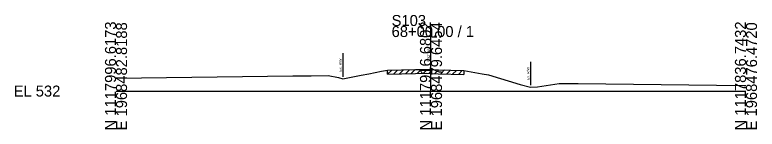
# Model space of a CAD drawing. Extents: x -26 to 163, y -10 to 24018.
# Drawn here: x -25.7 to 162.8, y 15990.3 to 16019.4 of the extents above; entities that cross this region are included whole.
import ezdxf

# ---------------------------------------------------------------- set-up
doc = ezdxf.new("R2010")
doc.units = 0
for name, color, linetype in [('RD_GPK_XS_Cell', 7, 'Continuous'), ('RD_XS_ExGround', 7, 'Continuous'), ('RD_XS_ExPaveRet', 7, 'Continuous'), ('RD_XS_ExRW', 7, 'Continuous'), ('RD_XS_TX_Elev_EX', 7, 'Continuous')]:
    doc.layers.add(name, color=color, linetype=linetype)

msp = doc.modelspace()

# ---------------------------------------------------------------- linework, layer by layer
at = {"layer": 'RD_GPK_XS_Cell'}
for p, q in [((80, 16000), (80, 16016.54)), ((0, 16000), (80, 16000)), ((80, 16000), (160, 16000))]:
    msp.add_line(p, q, dxfattribs=at)
at = {"layer": 'RD_XS_ExGround'}
msp.add_lwpolyline([(0, 16003.27), (44.87, 16003.84), (49.53, 16003.83), (53.88, 16003.99), (56.48, 16003.42), (57.59, 16003.13), (62.3, 16004.03), (64.18, 16004.41), (67.47, 16005.03), (68.99, 16005.29), (76.08, 16005.45), (78.94, 16005.51), (80, 16005.48), (81.79, 16005.42), (88.3, 16005.2), (92.96, 16004.38), (94.63, 16004.09), (102.66, 16001.66), (105.25, 16000.96), (107.06, 16001.11), (112.53, 16001.9), (117.34, 16001.89), (159.52, 16001.41), (160, 16001.41)], dxfattribs=at)
at = {"layer": 'RD_XS_ExPaveRet'}
for p, q in [((68.99, 16004.29), (70.02, 16005.31)), ((68.99, 16004.29), (68.99, 16005.29)), ((70.49, 16004.32), (71.52, 16005.35)), ((71.99, 16004.36), (73.02, 16005.38)), ((73.49, 16004.39), (74.52, 16005.42)), ((74.99, 16004.43), (76.02, 16005.45)), ((76.49, 16004.46), (77.51, 16005.48)), ((77.99, 16004.49), (79.01, 16005.51)), ((79.49, 16004.5), (80.46, 16005.46)), ((80.99, 16004.45), (81.96, 16005.41)), ((82.49, 16004.4), (83.46, 16005.36)), ((83.99, 16004.35), (84.96, 16005.31)), ((85.49, 16004.3), (86.46, 16005.26)), ((86.99, 16004.25), (87.96, 16005.22)), ((88.3, 16005.2), (88.3, 16004.2)), ((68.99, 16004.29), (76.08, 16004.45)), ((76.08, 16004.45), (78.94, 16004.51)), ((78.94, 16004.51), (80, 16004.48)), ((80, 16004.48), (81.79, 16004.42)), ((81.79, 16004.42), (88.3, 16004.2))]:
    msp.add_line(p, q, dxfattribs=at)
at = {"layer": 'RD_XS_ExRW'}
for p, q in [((57.59, 16009.63), (57.59, 16003.63)), ((105.25, 16007.46), (105.25, 16001.46))]:
    msp.add_line(p, q, dxfattribs=at)

# ---------------------------------------------------------------- texts
at = {"layer": 'RD_GPK_XS_Cell'}
for s, p in [('S103', (70, 16016.54)), ('68+00.00 / 1', (70, 16013.74)), ('EL 532', (-26, 15998.6))]:
    msp.add_text(s, height=2.8, dxfattribs=at).set_placement(p)
for s, p in [('N 1117996.6173', (0, 15990)), ('E 1968482.8188', (2.8, 15990)), ('N 1117916.6802', (80, 15990)), ('E 1968479.6454', (82.8, 15990)), ('N 1117836.7432', (160, 15990)), ('E 1968476.4720', (162.8, 15990))]:
    msp.add_text(s, height=2.8, rotation=90, dxfattribs=at).set_placement(p)
at = {"layer": 'RD_XS_ExRW'}
for p in [(57.34, 16004.97), (105, 16002.8)]:
    msp.add_text('Ex. R/W ', height=0.65, rotation=90, dxfattribs=at).set_placement(p)
at = {"layer": 'RD_XS_TX_Elev_EX'}
msp.add_text('537.48', height=0.8, rotation=90, dxfattribs=at).set_placement((79.9, 16007.48))

doc.saveas('drawing.dxf')
